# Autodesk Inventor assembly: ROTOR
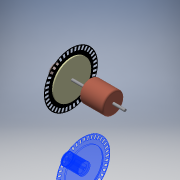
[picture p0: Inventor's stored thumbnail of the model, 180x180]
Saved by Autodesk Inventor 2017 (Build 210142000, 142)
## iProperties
Created: 2013-12
Part Number: ROTOR
Material: Générique
Document SubType Name: Assembly
Designer: Bruno
Mass: 82.8718 g
Surface Area: 148.108 cm^2
Volume: 15.0206 cm^3
Density: 5.51721 g/cm^3
Sending System: SolidWorks 2013
Last Author: christophe
Last Saved: 2014-02-15
Author: Bruno
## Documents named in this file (3)
- D:\Cours\1-Cours-2018-19\1Ssi\7- EDC-mvt\Haptique-2017\Reel-Inventor\ROTOR.iam
- D:\Cours\1-Cours-2018-19\1Ssi\7- EDC-mvt\Haptique-2017\Reel-Inventor\ROTOR.ipt
- D:\Cours\1-Cours-2018-19\1Ssi\7- EDC-mvt\Haptique-2017\Reel-Inventor\ROUE CODEUSE.ipt
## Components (2 placed, 2 different names)
1. ROTOR:1
2. ROUE CODEUSE:1
